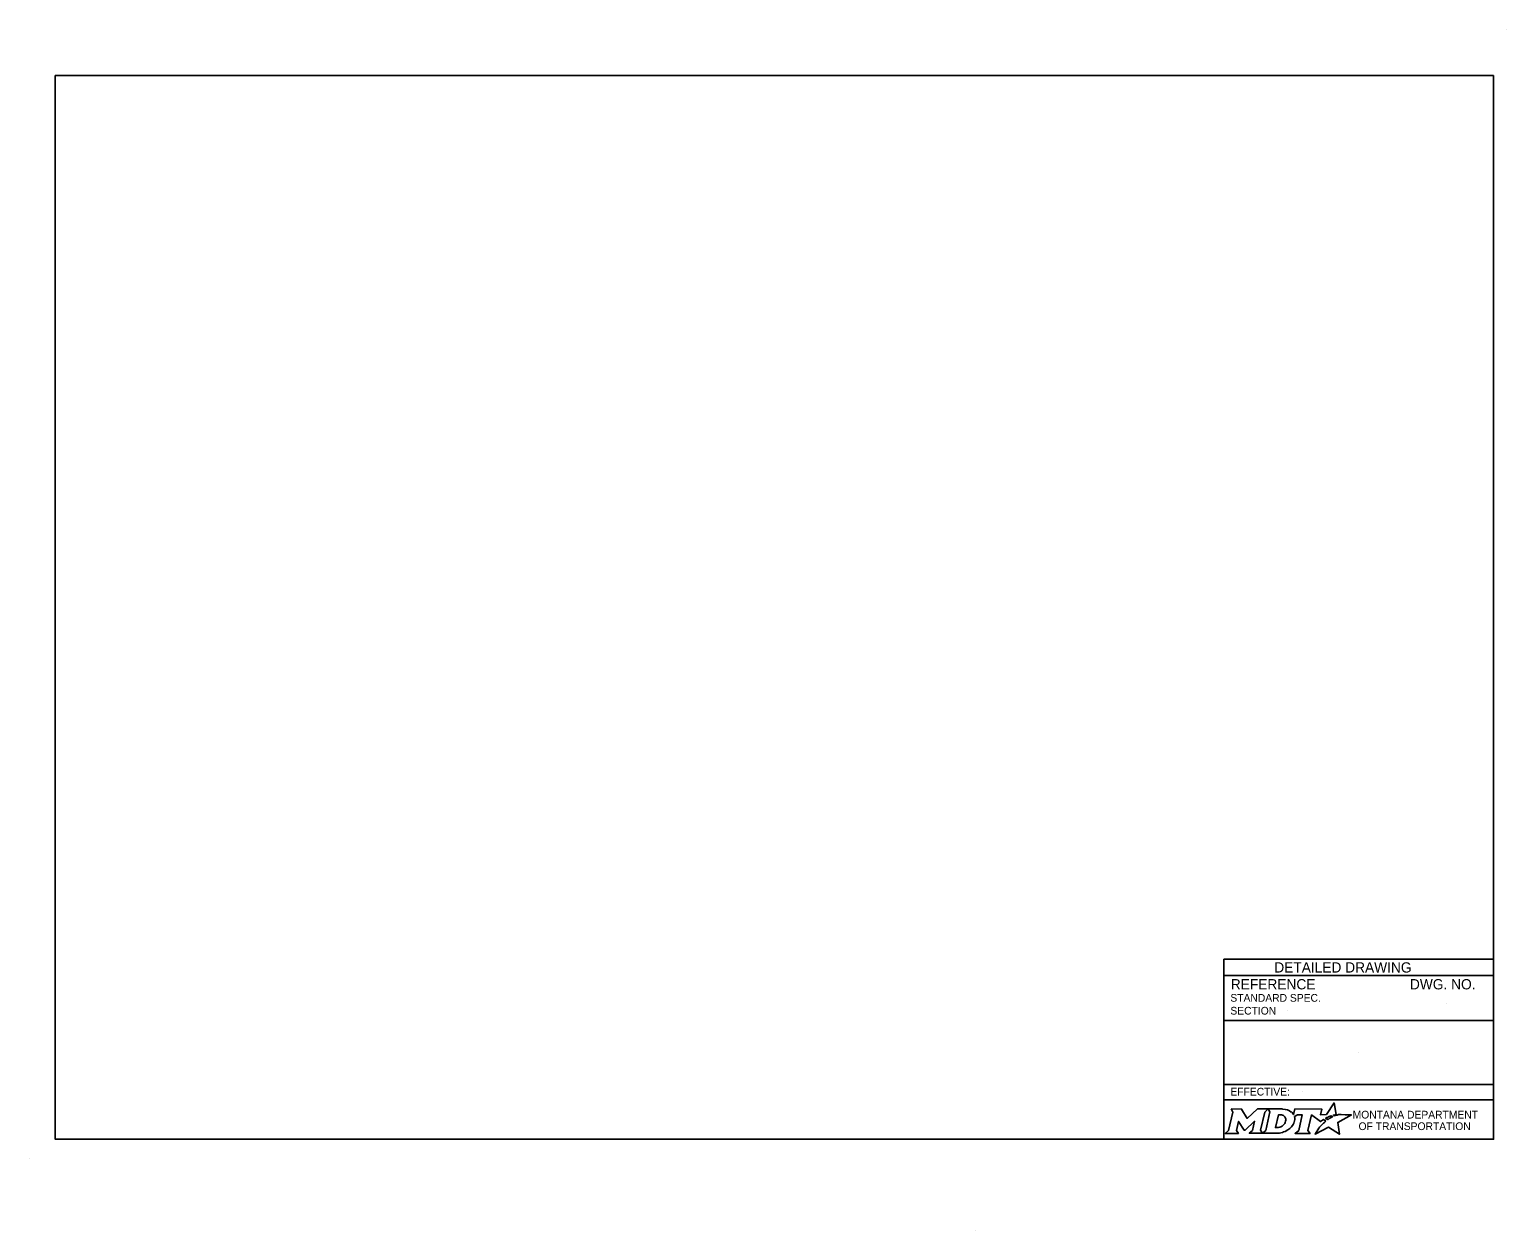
# Model space of a CAD drawing. Extents: x 49991.4 to 50021, y 49987.6 to 50011.4.
# Drawn here: x 50009.54 to 50021.04, y 49999.18 to 50008.52 of the extents above; entities that cross this region are included whole.
import ezdxf

# ---------------------------------------------------------------- set-up
doc = ezdxf.new("R2010")
doc.units = 0
for name, color, linetype in [('Default', 7, 'Continuous'), ('Level 1', 7, 'Continuous'), ('Level 4', 7, 'Continuous')]:
    doc.layers.add(name, color=color, linetype=linetype)

msp = doc.modelspace()

# ---------------------------------------------------------------- linework, layer by layer
at = {"layer": 'Default'}
for points in [[(50018.893, 50000.121), (50018.907, 50000.097), (50018.874, 49999.954), (50018.848, 49999.931), (50018.95, 49999.931), (50018.936, 49999.954), (50018.952, 50000.024), (50018.996, 49999.955), (50019.002, 49999.955), (50019.077, 50000.025), (50019.06, 49999.954), (50019.035, 49999.932), (50019.137, 49999.932), (50019.123, 49999.955), (50019.156, 50000.097)], [(50019.156, 50000.097), (50019.182, 50000.121), (50019.099, 50000.121), (50019.02, 50000.048), (50018.975, 50000.12), (50018.893, 50000.121)], [(50019.295, 50000.121), (50019.182, 50000.121), (50019.196, 50000.098), (50019.163, 49999.954), (50019.137, 49999.932), (50019.248, 49999.932)], [(50019.319, 50000.034), (50019.318, 50000.026), (50019.315, 50000.017), (50019.311, 50000.008), (50019.305, 50000.001), (50019.299, 49999.994), (50019.291, 49999.988), (50019.282, 49999.983), (50019.273, 49999.979), (50019.264, 49999.977), (50019.255, 49999.976), (50019.239, 49999.976), (50019.263, 50000.076), (50019.279, 50000.076), (50019.286, 50000.075), (50019.294, 50000.073), (50019.301, 50000.07), (50019.307, 50000.066), (50019.311, 50000.061), (50019.315, 50000.055), (50019.318, 50000.049), (50019.319, 50000.042), (50019.32, 50000.038), (50019.319, 50000.034)], [(50019.7, 50000.068), (50019.69, 50000.074), (50019.702, 50000.076), (50019.713, 50000.078), (50019.696, 50000.168), (50019.636, 50000.077), (50019.589, 50000.076), (50019.599, 50000.12), (50019.39, 50000.121), (50019.38, 50000.078), (50019.374, 50000.086)], [(50019.387, 50000.062), (50019.411, 50000.075), (50019.448, 50000.075), (50019.42, 49999.954), (50019.392, 49999.931), (50019.508, 49999.931), (50019.491, 49999.954), (50019.52, 50000.075), (50019.591, 50000.023), (50019.612, 50000.038), (50019.632, 50000.027)], [(50019.576, 49999.971), (50019.561, 49999.947), (50019.556, 49999.939), (50019.55, 49999.931), (50019.548, 49999.926), (50019.653, 49999.979), (50019.737, 49999.924), (50019.724, 50000.017), (50019.831, 50000.075), (50019.782, 50000.076), (50019.751, 50000.077), (50019.731, 50000.077), (50019.724, 50000.075), (50019.719, 50000.074), (50019.711, 50000.072), (50019.7, 50000.068)], [(50019.65, 50000.04), (50019.648, 50000.039), (50019.629, 50000.048), (50019.639, 50000.054), (50019.644, 50000.056), (50019.652, 50000.06), (50019.658, 50000.063), (50019.666, 50000.066), (50019.673, 50000.068), (50019.685, 50000.061), (50019.681, 50000.059), (50019.676, 50000.056), (50019.672, 50000.054), (50019.667, 50000.051), (50019.665, 50000.05), (50019.662, 50000.049), (50019.66, 50000.047), (50019.658, 50000.046), (50019.655, 50000.044), (50019.652, 50000.042), (50019.65, 50000.04)], [(50019.293, 49999.939), (50019.302, 49999.942), (50019.315, 49999.947), (50019.335, 49999.958)], [(50019.59, 49999.987), (50019.59, 49999.987)]]:
    msp.add_lwpolyline(points, dxfattribs=at)
for centre, radius, start, end in [((50019.319, 50000.042), 0.0709, 339.5329, 15.8582), ((50019.274, 50000.059), 0.118, 300.9103, 339.1383)]:
    msp.add_arc(centre, radius, start, end, dxfattribs=at)
for centre, major_axis, ratio, start_param, end_param in [((50019.293, 50000.073), (0.0834, -0.0037), 0.568097, 0.61298, 1.570796), ((50019.349, 50000.081), (0.0361, -0.0295), 0.469099, 1.225588, 1.570796), ((50019.583, 49999.979), (-0.00694, -0.00806), 0.008222, 0, 3.137361), ((50019.6, 49999.997), (-0.0098, -0.0102), 0.016458, 3.141593, 6.279097), ((50019.621, 50000.017), (-0.0112, -0.0097), 0.021651, 3.157348, 6.283185), ((50019.248, 50000.08), (0, 0.148), 0.987302, 3.139398, 3.456847)]:
    msp.add_ellipse(centre, major_axis=major_axis, ratio=ratio, start_param=start_param, end_param=end_param, dxfattribs=at)
at = {"layer": 'Level 1'}
for p, q in [((50021.038, 50008.524), (50021.038, 50008.524)), ((50009.537, 49999.736), (50009.537, 49999.736)), ((50016.9, 49999.176), (50016.9, 49999.176))]:
    msp.add_line(p, q, dxfattribs=at)
msp.add_lwpolyline([(50020.938, 50008.165), (50009.737, 50008.165), (50009.737, 49999.886), (50020.938, 49999.886)], close=True, dxfattribs=at)
at = {"layer": 'Level 4'}
for p, q in [((50020.938, 50001.286), (50018.838, 50001.286)), ((50018.838, 50001.286), (50018.838, 49999.886)), ((50020.938, 50001.161), (50018.838, 50001.161)), ((50019.332, 50000.886), (50019.332, 50000.886)), ((50020.574, 50000.946), (50020.574, 50000.946)), ((50020.938, 50000.811), (50018.838, 50000.811)), ((50019.888, 50000.562), (50019.888, 50000.562)), ((50020.938, 50000.312), (50018.838, 50000.312)), ((50020.938, 50000.193), (50018.838, 50000.193)), ((50019.453, 50000.256), (50019.453, 50000.256))]:
    msp.add_line(p, q, dxfattribs=at)

# ---------------------------------------------------------------- texts
at = {"layer": 'Default'}
for s, p in [('MONTANA DEPARTMENT', (50019.84, 50000.047)), ('OF TRANSPORTATION', (50019.886, 49999.957))]:
    msp.add_text(s, height=0.06, rotation=360, dxfattribs=at).set_placement(p)
at = {"layer": 'Level 4'}
for s, height, p in [('DETAILED DRAWING', 0.0799, (50019.23, 50001.183)), ('REFERENCE', 0.08, (50018.891, 50001.052)), ('DWG. NO.', 0.08, (50020.286, 50001.052)), ('STANDARD SPEC.', 0.06, (50018.888, 50000.956)), ('SECTION', 0.06, (50018.888, 50000.856)), ('EFFECTIVE:', 0.06, (50018.888, 50000.226))]:
    msp.add_text(s, height=height, dxfattribs=at).set_placement(p)

doc.saveas('drawing.dxf')
